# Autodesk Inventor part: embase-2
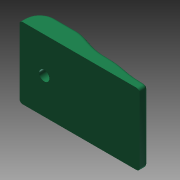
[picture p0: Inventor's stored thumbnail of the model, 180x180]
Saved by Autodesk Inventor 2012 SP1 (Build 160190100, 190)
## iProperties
Created: 2012-06
Part Number: embase-2
Material: Default
Document SubType Name: Modeling
Designer: Bruno
Density: 1 g/cm^3
Author: Bruno
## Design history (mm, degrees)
sketch "Esquisse1"
  geometry: L1 (0, 0)-(118, 0); L2 (118, 0)-(118, 5); L3 (33.666, 20)-(15, 20); L4 (0, 5)-(0, 0); L5 (0, 0)-(118, 0); A1 r 15 centre (15, 5) between (15, 20) and (0, 5); 5 further points
  constraints: 10 end point, 3 horizontal, 2 parallel, 2 point on circle, 2 point on line, 2 tangent, 1 centre point, 1 perpendicular, 1 vertical, 8 other
  dimensions: "d2" = 15 radius of A1; "d19" = 118 distance of L1.start L1.end; "d21" = 5 distance of L1.end L2.end
extrude "Extrusion1" new body sketch "Esquisse1" stored distance "d3" = 70; taper "d4" = 0 deg
fillet "Congé1" dims "d5" = 3
sketch "Esquisse4"
  geometry: L1 (0, 0)-(0, -64) reference; L2 (18.666, -32)-(18.666, 0) reference; L3 (0, -32)-(18.666, -32); 2 further points
  constraints: 2 end point, 2 midpoint, 1 perpendicular
hole "Perçage1" sketch "Esquisse4" at (9.333, -32) diameter "d9" = 10; stored, may be unused: countersink angle "d13" = 90 deg, drill point angle "d15" = 118 deg; dims "d10" = 6, "d11" = 14, "d12" = 5, "d14" = 50
node "Solide1"
